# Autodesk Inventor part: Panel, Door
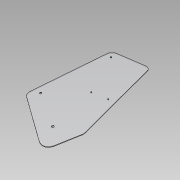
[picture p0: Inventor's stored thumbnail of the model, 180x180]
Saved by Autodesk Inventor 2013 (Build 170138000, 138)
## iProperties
Shininess: 64.0
Length Units: 11269
Angle Units: 11279
Time Units: 11290
Mass Units: 11283
Length Display Precision: 3
Angle Display Precision: 2
Compacted: True
Part Number: Panel, Door
Document SubType Name: Modeling
Created: 2005-02
Material: Polycarbonate, Clear
Designer: =<Author>
Manufacturer: Standard
Standards Organization: Custom
Description: =<Part Number>
Density: 1.2 g/cm^3
Mass: 5980.08 g
Surface Area: 12740.7 cm^2
Volume: 4983.4 cm^3
Density: 0.0
Volumn: 0.0
Area: 0.0
PropertySet Name: Model Information
Control State: 0
Master: False
Checked Out: False
Author: PVitaliy
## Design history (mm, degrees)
sketch "Sketch1"
  geometry: L1 (0, 1005)-(455, 1005); L2 (0, 1005)-(0, 0); L3 (0, 0)-(555, -258); L4 (555, -258)-(630, 15); L5 (630, 15)-(455, 1005); L6 (74, 910)-(74, 86.905); L7 (74, 86.905)-(436.723, -81.713); L8 (496.365, 397.579)-(343.731, 370.598); C1 r 10 at (74, 910); C2 r 10 at (74, 86.905); C3 r 10 at (436.723, -81.713); C4 r 6 at (343.731, 370.598); C5 r 6 at (496.365, 397.579)
  constraints: 16 end point, 5 centre point, 5 coincident, 3 equal radius, 2 parallel, 2 perpendicular, 1 vertical, 1 other
  dimensions: "d33" = 455 distance of L1.start L1.end; "d34" = 1005 distance of L1.start L2.end; "d35" = 630 distance from line of L4.end L2; "d36" = 258 vertical distance of L2.end L3.end; "d37" = 75 horizontal distance of L3.end L4.end; "d38" = 990 distance from line of L4.end L1; "d39" = 74 distance between parallel lines of L6 L2; "d40" = 95 distance from line of L6.start L1; "d41" = 110 distance between parallel lines of L3 L7; "d42" = 400 distance of L6.end L7.end; "d43" = 20 diameter of C1; "d45" = 155 distance of L8.start L8.end; "d46" = 65 distance from line of L5 L8.start; "d47" = 400 distance from line of L4.end L8; "d48" = 12 diameter of C4
extrude "Extrusion1" new body sketch "Sketch1" taper "d50" = 0 deg; distance "Thickness" = 8
fillet "Fillet1" dims "d51" = 65
body "Solid1"
body "Solid2"
other parameters: "Толщина" = 8, "Радиус_гибки" = 8 (= Толщина), "Ширина_просечки" = 8 (= Толщина), "Глубина_просечки" = 4 (= 0.5 x Толщина), "Размер_высечки" = 32 (= 4 x Толщина), "Зазор_стыка" = 0.01, "Минимальный_остаток" = 16 (= 2 x Толщина), "Радиус_перехода" = 8 (= Радиус_гибки), "d2" = 8 (= Радиус_гибки), "JacobiRadiusSize" = 8 (= Радиус_гибки), "GapSize" = 8 (= Толщина)
